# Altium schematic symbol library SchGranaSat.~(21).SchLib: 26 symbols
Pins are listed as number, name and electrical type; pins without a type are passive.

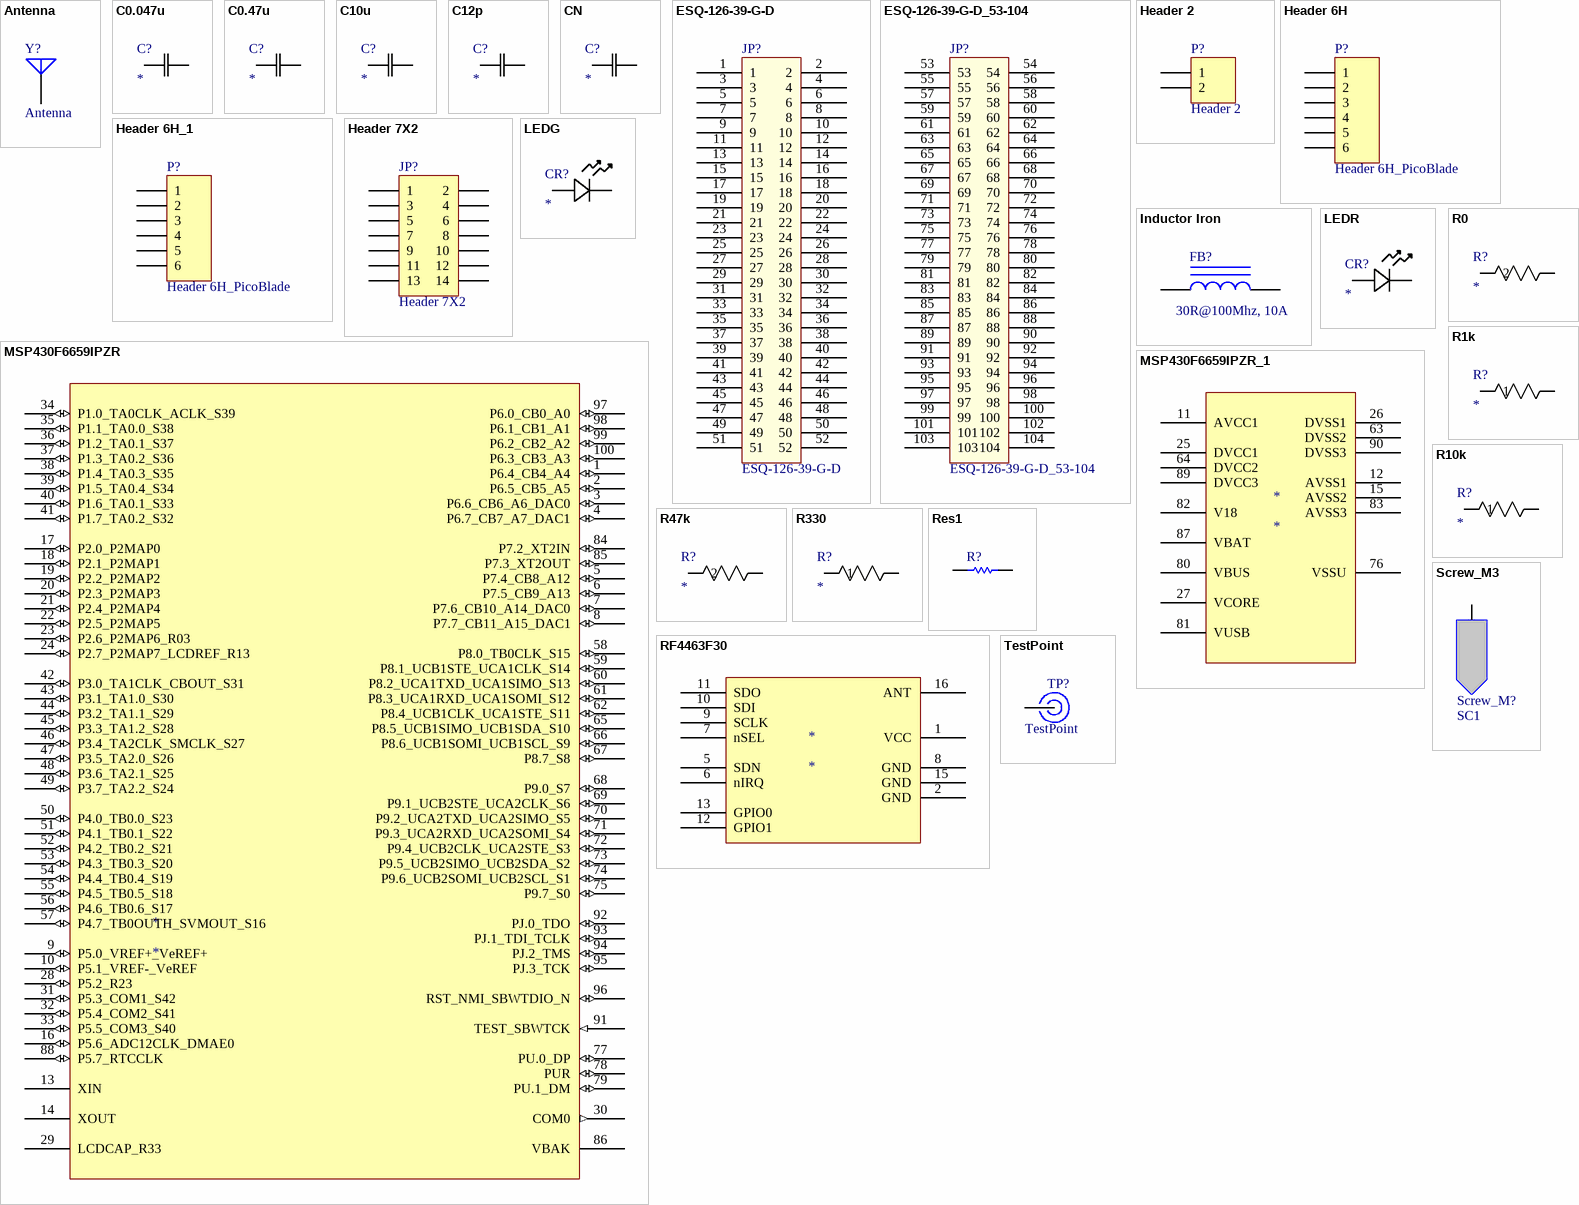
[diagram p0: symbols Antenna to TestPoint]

## Antenna
designator Y?
Generic Antenna
footprint PIN1 (Generic Antenna; 1 Lead)
pins: 1 A

## C0.047u
designator C?
Imported; Manufacturer_Part_Number: 06033C473KAT2A; Vendor: AVX Corporation; Built_By: EMA_UL_Team; Type: DEV; C: Copyright (C) 2015 Accelerated Designs. All rights reserved
footprint C0.047u
pins: 1, 2

## C0.47u
designator C?
Imported; Manufacturer_Part_Number: C1608X7R1H474K080AC; Vendor: TDK; Built_By: EMA_UL_Team; Type: DEV; C: Copyright (C) 2015 Accelerated Designs. All rights reserved
footprint C0.47u
pins: 1, 2

## C10u
designator C?
Imported; Manufacturer_Part_Number: TAJR106K006RNJ; Vendor: AVX Corporation; Built_By: EMA_UL_Team; Type: DEV; C: Copyright (C) 2015 Accelerated Designs. All rights reserved
footprint C10u
pins: 1, 2

## C12p
designator C?
Imported; Manufacturer_Part_Number: GCM1885C1H120JA16D; Vendor: Murata; Built_By: EMA_UL_Team; Type: DEV; C: Copyright (C) 2015 Accelerated Designs. All rights reserved
footprint C12p
pins: 1, 2

## CN
designator C?
Imported; Manufacturer_Part_Number: GCM188R71H104KA57D; Vendor: Murata; Built_By: EMA_UL_Team; Type: DEV; C: Copyright (C) 2015 Accelerated Designs. All rights reserved
footprint G-188
pins: 1, 2

## ESQ-126-39-G-D
designator JP?
Cubesat Header Connector; Shop: es.rs-online.com; Localización: Último cajón cajonera blanca entre Pablo y Luis; Reference: 254-6132
footprint ESQ-126-39-G-D (Cubesat Connector; Header; 26x2 Position)
pins: 1, 2, 3, 4, 5, 6, 7, 8, 9, 10, 11, 12, 13, 14, 15, 16, 17, 18, 19, 20, 21, 22, 23, 24, 25, 26, 27, 28, 29, 30, 31, 32, 33, 34, 35, 36, 37, 38, 39, 40, 41, 42, 43, 44, 45, 46, 47, 48, 49, 50, 51, 52

## ESQ-126-39-G-D_53-104
designator JP?
Cubesat Header Connector; Shop: es.rs-online.com; Localización: Último cajón cajonera blanca entre Pablo y Luis; Reference: 254-6132
footprint ESQ-126-39-G-D_53_104 (Cubesat Connector; Header; 26x2 Position)
pins: 53, 54, 55, 56, 57, 58, 59, 60, 61, 62, 63, 64, 65, 66, 67, 68, 69, 70, 71, 72, 73, 74, 75, 76, 77, 78, 79, 80, 81, 82, 83, 84, 85, 86, 87, 88, 89, 90, 91, 92, 93, 94, 95, 96, 97, 98, 99, 100, 101, 102, 103, 104

## Header 2
designator P?
Header, 2-Pin
footprint HDR1X2 (Connector; Header; 2 Position)
signal-integrity model Connector
pins: 1, 2

## Header 6H
designator P?, comment Header 6H_PicoBlade
Header, 6-Pin, Left Angle
footprint HDR1X6H (Connector; Header; 6 Position; Right Angle)
signal-integrity model Connector
pins: 1, 2, 3, 4, 5, 6

## Header 6H_1
designator P?, comment Header 6H_PicoBlade
Header, 6-Pin, Right Angle
signal-integrity model Connector
footprint HDR1X6H (Connector; Header; 6 Position; Right Angle)
pins: 1, 2, 3, 4, 5, 6

## Header 7X2
designator JP?
Header, 7-Pin, Dual row
footprint HDR2X7 (Connector; Header; 7x2 Position)
signal-integrity model Connector
pins: 1, 2, 3, 4, 5, 6, 7, 8, 9, 10, 11, 12, 13, 14

## Inductor Iron
designator FB?  value 30R@100Mhz, 10A
Magnetic-Core Inductor
simulation model INDUCTOR (Inductor)
signal-integrity model Inductor Iron
footprint INDC3216 (Chip Inductor, Body 3.2x1.6mm, IPC High Density)
pins: 1, 2

## LEDG
designator CR?
Imported; Manufacturer_Part_Number: TLMP1100-GS08; Vendor: Vishay; Built_By: EMA_UL_Team; Type: DEV; C: Copyright (C) 2015 Accelerated Designs. All rights reserved
footprint LEDG
pins: 1, 2

## LEDR
designator CR?
Imported; Manufacturer_Part_Number: TLMS1100-GS08; Vendor: Vishay; Built_By: EMA_UL_Team; Type: DEV; C: Copyright (C) 2015 Accelerated Designs. All rights reserved
footprint LEDR
pins: 1, 2

## MSP430F6659IPZR
designator *
footprint MSP430F6659IPZR
pins: 1 P6.4_CB4_A4 (io), 2 P6.5_CB5_A5 (io), 3 P6.6_CB6_A6_DAC0 (io), 4 P6.7_CB7_A7_DAC1 (io), 5 P7.4_CB8_A12 (io), 6 P7.5_CB9_A13 (io), 7 P7.6_CB10_A14_DAC0 (io), 8 P7.7_CB11_A15_DAC1 (io), 9 P5.0_VREF+_VeREF+ (io), 10 P5.1_VREF-_VeREF (io), 13 XIN, 14 XOUT, 16 P5.6_ADC12CLK_DMAE0 (io), 17 P2.0_P2MAP0 (io), 18 P2.1_P2MAP1 (io), 19 P2.2_P2MAP2 (io), 20 P2.3_P2MAP3 (io), 21 P2.4_P2MAP4 (io), 22 P2.5_P2MAP5 (io), 23 P2.6_P2MAP6_R03 (io), 24 P2.7_P2MAP7_LCDREF_R13 (io), 28 P5.2_R23 (io), 29 LCDCAP_R33, 30 COM0 (out), 31 P5.3_COM1_S42 (io), 32 P5.4_COM2_S41 (io), 33 P5.5_COM3_S40 (io), 34 P1.0_TA0CLK_ACLK_S39 (io), 35 P1.1_TA0.0_S38 (io), 36 P1.2_TA0.1_S37 (io), 37 P1.3_TA0.2_S36 (io), 38 P1.4_TA0.3_S35 (io), 39 P1.5_TA0.4_S34 (io), 40 P1.6_TA0.1_S33 (io), 41 P1.7_TA0.2_S32 (io), 42 P3.0_TA1CLK_CBOUT_S31 (io), 43 P3.1_TA1.0_S30 (io), 44 P3.2_TA1.1_S29 (io), 45 P3.3_TA1.2_S28 (io), 46 P3.4_TA2CLK_SMCLK_S27 (io), 47 P3.5_TA2.0_S26 (io), 48 P3.6_TA2.1_S25 (io), 49 P3.7_TA2.2_S24 (io), 50 P4.0_TB0.0_S23 (io), 51 P4.1_TB0.1_S22 (io), 52 P4.2_TB0.2_S21 (io), 53 P4.3_TB0.3_S20 (io), 54 P4.4_TB0.4_S19 (io), 55 P4.5_TB0.5_S18 (io), 56 P4.6_TB0.6_S17 (io), 57 P4.7_TB0OUTH_SVMOUT_S16 (io), 58 P8.0_TB0CLK_S15 (io), 59 P8.1_UCB1STE_UCA1CLK_S14 (io), 60 P8.2_UCA1TXD_UCA1SIMO_S13 (io), 61 P8.3_UCA1RXD_UCA1SOMI_S12 (io), 62 P8.4_UCB1CLK_UCA1STE_S11 (io), 65 P8.5_UCB1SIMO_UCB1SDA_S10 (io), 66 P8.6_UCB1SOMI_UCB1SCL_S9 (io), 67 P8.7_S8 (io), 68 P9.0_S7 (io), 69 P9.1_UCB2STE_UCA2CLK_S6 (io), 70 P9.2_UCA2TXD_UCA2SIMO_S5 (io), 71 P9.3_UCA2RXD_UCA2SOMI_S4 (io), 72 P9.4_UCB2CLK_UCA2STE_S3 (io), 73 P9.5_UCB2SIMO_UCB2SDA_S2 (io), 74 P9.6_UCB2SOMI_UCB2SCL_S1 (io), 75 P9.7_S0 (io), 77 PU.0_DP (io), 78 PUR (io), 79 PU.1_DM (io), 84 P7.2_XT2IN (io), 85 P7.3_XT2OUT (io), 86 VBAK, 88 P5.7_RTCCLK (io), 91 TEST_SBWTCK (in), 92 PJ.0_TDO (io), 93 PJ.1_TDI_TCLK (io), 94 PJ.2_TMS (io), 95 PJ.3_TCK (io), 96 RST_NMI_SBWTDIO_N (io), 97 P6.0_CB0_A0 (io), 98 P6.1_CB1_A1 (io), 99 P6.2_CB2_A2 (io), 100 P6.3_CB3_A3 (io)

## MSP430F6659IPZR_1
designator *
footprint MSP430F6659IPZR
pins: 11 AVCC1, 12 AVSS1, 15 AVSS2, 25 DVCC1, 26 DVSS1, 27 VCORE, 63 DVSS2, 64 DVCC2, 76 VSSU, 80 VBUS, 81 VUSB, 82 V18, 83 AVSS3, 87 VBAT, 89 DVCC3, 90 DVSS3

## R0
designator R?
Imported; Manufacturer_Part_Number: WSL12065L000FEA18; Vendor: Vishay; Built_By: EMA_UL_Team; C: Copyright (C) 2015 Accelerated Designs. All rights reserved
footprint R0
pins: 1, 2

## R1k
designator R?
Imported; Manufacturer_Part_Number: MCT0603MC1001FP500; Vendor: Vishay; Built_By: EMA_UL_Team; C: Copyright (C) 2015 Accelerated Designs. All rights reserved
footprint 0603
pins: 1, 2

## R10k
designator R?
Imported; Manufacturer_Part_Number: RNCP0603FTD10K0; Vendor: Stackpole International; Built_By: EMA_UL_Team; C: Copyright (C) 2015 Accelerated Designs. All rights reserved
footprint STA_RNCP0603
pins: 1, 2

## R47k
designator R?
Imported; Manufacturer_Part_Number: TNPW060347K0BEEA; Vendor: Vishay; Built_By: EMA_UL_Team; C: Copyright (C) 2015 Accelerated Designs. All rights reserved
footprint RC0603N
pins: 1, 2

## R330
designator R?
Imported; Manufacturer_Part_Number: CRCW0603330RFKEAHP; Vendor: Vishay; Built_By: EMA_UL_Team; C: Copyright (C) 2015 Accelerated Designs. All rights reserved
footprint RES_CRCW_0603
pins: 1, 2

## Res1
designator R?
Resistor
simulation model RESISTOR (Resistor)
signal-integrity model Res
footprint R
pins: 1, 2

## RF4463F30
designator *
pins: 1 VCC, 2 GND, 5 SDN, 6 nIRQ, 7 nSEL, 8 GND, 9 SCLK, 10 SDI, 11 SDO, 12 GPIO1, 13 GPIO0, 15 GND, 16 ANT

## Screw_M3
designator Screw_M?, comment SC1
Main CubeSAT bus
footprint Screw_M3 (Main CubeSAT bus M3 screw)
pins: 1

## TestPoint
designator TP?  PCB DECAL: TestPoint
Punto de prueba de 3x3mm
footprint TESTPOINT_1.5x1.5mm (Punto de test de 1.5x1.5mm)
footprint TESTPOINT_1.5x1.5mm (Punto de test de 1.5x1.5mm)
pins: 1 (power)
